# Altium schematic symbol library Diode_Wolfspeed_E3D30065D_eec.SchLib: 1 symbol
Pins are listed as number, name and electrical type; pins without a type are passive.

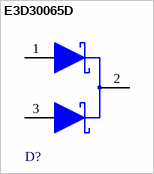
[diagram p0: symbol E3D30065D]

## E3D30065D
designator D?  (value not drawn)
pins: 1 1 ANODE, 2 COMMON CATHODE, 3 2 ANODE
